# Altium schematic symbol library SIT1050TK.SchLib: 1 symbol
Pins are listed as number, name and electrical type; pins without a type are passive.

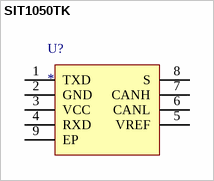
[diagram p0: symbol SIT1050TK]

## SIT1050TK
designator U?
CAN IC
footprint SON65P300X300X100-9N
pins: 1 TXD, 2 GND, 3 VCC, 4 RXD, 5 VREF, 6 CANL, 7 CANH, 8 S, 9 EP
